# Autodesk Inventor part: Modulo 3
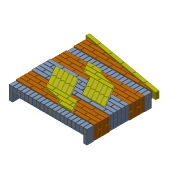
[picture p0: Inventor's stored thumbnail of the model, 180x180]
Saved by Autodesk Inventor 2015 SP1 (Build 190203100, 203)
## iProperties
Created: 2015-04
Part Number: Modulo 3
Material: Generic
Document SubType Name: Modeling
Designer: treina2
Density: 1 g/cm^3
Appearance: Default
Author: treina2
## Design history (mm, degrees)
sketch "Sketch1"
  geometry: L1 (994.875, 828.16)-(1008.247, 805) reference; L2 (1109.875, 329)-(1109.875, 387) reference; L3 (1109.875, 387)-(869.875, 387) reference; L4 (869.875, 387)-(869.875, 329) reference; L5 (340.73, 319)-(244.875, 319) reference; L6 (244.875, 319)-(244.875, 261) reference; L7 (939.842, 183)-(836.807, 183) reference; L8 (939.842, 183)-(744.875, 183) reference; L9 (744.875, 183)-(744.875, 125) reference; L10 (861.322, 319)-(836.807, 319) reference; L11 (739.101, 329)-(859.875, 329) reference; L12 (859.875, 329)-(859.875, 387) reference; L13 (859.875, 387)-(705.615, 387) reference; L14 (1234.875, 941)-(994.875, 941) reference; L15 (994.875, 941)-(994.875, 999) reference; L16 (994.875, 999)-(1234.875, 999) reference; L17 (1234.875, 999)-(1234.875, 941) reference; L18 (619.875, 1134)-(859.875, 1134) reference; L19 (859.875, 1134)-(859.875, 1192) reference; L20 (859.875, 1192)-(619.875, 1192) reference; L21 (619.875, 1192)-(619.875, 1134) reference; L22 (136.5, 0)-(136.5, 115) reference; L23 (136.5, 115)-(194.5, 115) reference; L24 (194.5, 115)-(194.5, 0) reference; L25 (194.5, 0)-(136.5, 0) reference; L26 (859.875, 125)-(973.328, 125) reference; L27 (494.875, 669)-(682.621, 669) reference; L28 (119.875, 465)-(256.437, 465) reference; L29 (301.47, 659)-(234.497, 659) reference; L30 (234.497, 659)-(335.632, 483.83) reference; L31 (335.632, 483.83)-(385.861, 512.83) reference; L32 (385.861, 512.83)-(301.47, 659) reference; L33 (-5.125, 261)-(234.875, 261) reference; L34 (234.875, 261)-(234.875, 319) reference; L35 (234.875, 319)-(-5.125, 319) reference; L36 (-5.125, 319)-(-5.125, 261) reference; L37 (832.83, 329)-(859.875, 329) reference; L38 (859.875, 329)-(859.875, 387) reference; L39 (859.875, 387)-(809.762, 387) reference; L40 (619.875, 193)-(642.243, 193) reference; L41 (340.73, 319)-(244.875, 319) reference; L42 (244.875, 319)-(244.875, 261) reference; L43 (619.875, 197.266)-(619.875, 193) reference; L44 (334.956, 329)-(301.47, 387) reference; L45 (494.875, 261)-(734.875, 261) reference; L46 (244.875, 261)-(369.875, 261) reference; L47 (491.996, 329)-(390.861, 504.17) reference; L48 (744.875, 261)-(849.113, 261) reference; L49 (900.582, 251)-(869.875, 251) reference; L50 (869.875, 251)-(869.875, 193) reference; L51 (385.763, 261)-(352.277, 319) reference; L52 (695.615, 193)-(859.875, 193) reference; L53 (859.875, 193)-(859.875, 251) reference; L54 (859.875, 251)-(619.875, 251) reference; L55 (619.875, 251)-(619.875, 207.447) reference; L56 (945.615, 193)-(1109.875, 193) reference; L57 (1109.875, 193)-(1109.875, 251) reference; L58 (1109.875, 251)-(912.129, 251) reference; L59 (906.355, 261)-(984.875, 261) reference; L60 (984.875, 261)-(984.875, 319) reference; L61 (984.875, 319)-(872.869, 319) reference; L62 (144.431, 659)-(119.875, 659) reference; L63 (119.875, 659)-(119.875, 601) reference; L64 (1234.875, 805)-(1008.247, 805) reference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; 3 further points
  constraints: 1806 end point, 395 horizontal, 258 vertical, 116 point on line, 1005 other
workplane "Work Plane1"
sketch "Sketch2"
  geometry: L1 (0, 1009)-(0, 1124) reference; L2 (0, 1124)-(58, 1124) reference; L3 (58, 1124)-(58, 1009) reference; L4 (58, 1009)-(0, 1009) reference; L5 (0, 0)-(0, 115) reference; L6 (0, 115)-(58, 115) reference; L7 (58, 115)-(58, 0) reference; L8 (58, 0)-(0, 0) reference; L9 (126.25, 1124)-(126.25, 1009) reference; L10 (68.25, 1124)-(126.25, 1124) reference; L11 (68.25, 1009)-(68.25, 1124) reference; L12 (126.25, 1009)-(68.25, 1009) reference; L13 (1354.75, 1124)-(1354.75, 1009) reference; L14 (1296.75, 1124)-(1354.75, 1124) reference; L15 (1296.75, 1009)-(1296.75, 1124) reference; L16 (1354.75, 1009)-(1296.75, 1009) reference; L17 (68.25, 0)-(68.25, 115) reference; L18 (68.25, 115)-(126.25, 115) reference; L19 (126.25, 115)-(126.25, 0) reference; L20 (126.25, 0)-(68.25, 0) reference; L21 (1296.75, 0)-(1296.75, 115) reference; L22 (1296.75, 115)-(1354.75, 115) reference; L23 (1354.75, 115)-(1354.75, 0) reference; L24 (1354.75, 0)-(1296.75, 0) reference; 1 further point
extrude "Extrusion2" new body sketch "Sketch2" distance "d6" = 240; taper "d7" = 0 deg
extrude "Extrusion3" new body sketch "Sketch2" distance "d8" = 240; taper "d9" = 0 deg
extrude "Extrusion4" new body sketch "Sketch2" distance "d10" = 240; taper "d11" = 0 deg
extrude "Extrusion5" new body sketch "Sketch2" distance "d12" = 240; taper "d13" = 0 deg
extrude "Extrusion6" new body sketch "Sketch2" distance "d14" = 115; taper "d15" = 0 deg
extrude "Extrusion7" new body sketch "Sketch2" distance "d16" = 115; taper "d17" = 0 deg
extrude "Extrusion8" new body sketch "Sketch1" distance "d24" = 115; taper "d25" = 0 deg
extrude "Extrusion9" new body sketch "Sketch1" distance "d26" = 240; taper "d27" = 0 deg
extrude "Extrusion10" new body sketch "Sketch1" distance "d28" = 240; taper "d29" = 0 deg
extrude "Extrusion11" new body sketch "Sketch1" distance "d30" = 115; taper "d31" = 0 deg
extrude "Extrusion12" new body sketch "Sketch1" distance "d32" = 115; taper "d33" = 0 deg
extrude "Extrusion13" new body sketch "Sketch1" distance "d34" = 115; taper "d35" = 0 deg
extrude "Extrusion14" new body sketch "Sketch1" distance "d36" = 115; taper "d37" = 0 deg
extrude "Extrusion15" new body sketch "Sketch1" distance "d38" = 115; taper "d39" = 0 deg
extrude "Extrusion16" new body sketch "Sketch1" distance "d40" = 115; taper "d41" = 0 deg
extrude "Extrusion17" new body sketch "Sketch1" distance "d42" = 115; taper "d43" = 0 deg
extrude "Extrusion18" new body sketch "Sketch1" distance "d44" = 115; taper "d45" = 0 deg
extrude "Extrusion19" new body sketch "Sketch1" distance "d46" = 115; taper "d47" = 0 deg
extrude "Extrusion20" new body sketch "Sketch1" distance "d48" = 115; taper "d49" = 0 deg
extrude "Extrusion21" new body sketch "Sketch1" distance "d50" = 115; taper "d51" = 0 deg
extrude "Extrusion22" new body sketch "Sketch1" distance "d52" = 115; taper "d53" = 0 deg
extrude "Extrusion23" new body sketch "Sketch1" distance "d54" = 115; taper "d55" = 0 deg
extrude "Extrusion24" new body sketch "Sketch1" distance "d56" = 115; taper "d57" = 0 deg
extrude "Extrusion25" new body sketch "Sketch1" distance "d58" = 115; taper "d59" = 0 deg
extrude "Extrusion26" new body sketch "Sketch1" distance "d60" = 115; taper "d61" = 0 deg
extrude "Extrusion27" new body sketch "Sketch1" distance "d62" = 115; taper "d63" = 0 deg
extrude "Extrusion28" new body sketch "Sketch1" distance "d64" = 115; taper "d65" = 0 deg
extrude "Extrusion29" new body sketch "Sketch1" distance "d66" = 115; taper "d67" = 0 deg
extrude "Extrusion30" new body sketch "Sketch1" distance "d68" = 115; taper "d69" = 0 deg
extrude "Extrusion31" new body sketch "Sketch1" distance "d70" = 115; taper "d71" = 0 deg
extrude "Extrusion32" new body sketch "Sketch1" distance "d72" = 115; taper "d73" = 0 deg
extrude "Extrusion33" new body sketch "Sketch1" distance "d74" = 115; taper "d75" = 0 deg
extrude "Extrusion34" new body sketch "Sketch1" distance "d76" = 115; taper "d77" = 0 deg
extrude "Extrusion35" new body sketch "Sketch1" distance "d78" = 115; taper "d79" = 0 deg
extrude "Extrusion36" new body sketch "Sketch1" distance "d80" = 115; taper "d81" = 0 deg
extrude "Extrusion37" new body sketch "Sketch1" distance "d82" = 240; taper "d83" = 0 deg
extrude "Extrusion38" new body sketch "Sketch1" distance "d84" = 240; taper "d85" = 0 deg
extrude "Extrusion39" new body sketch "Sketch1" distance "d86" = 240; taper "d87" = 0 deg
extrude "Extrusion40" new body sketch "Sketch1" distance "d88" = 240; taper "d89" = 0 deg
extrude "Extrusion41" new body sketch "Sketch1" distance "d90" = 115; taper "d91" = 0 deg
extrude "Extrusion42" new body sketch "Sketch1" distance "d92" = 115; taper "d93" = 0 deg
extrude "Extrusion43" new body sketch "Sketch1" distance "d94" = 115; taper "d95" = 0 deg
extrude "Extrusion44" new body sketch "Sketch1" distance "d96" = 115; taper "d97" = 0 deg
extrude "Extrusion45" new body sketch "Sketch1" distance "d98" = 115; taper "d99" = 0 deg
extrude "Extrusion46" new body sketch "Sketch1" distance "d100" = 115; taper "d101" = 0 deg
extrude "Extrusion47" new body sketch "Sketch1" distance "d102" = 115; taper "d103" = 0 deg
extrude "Extrusion48" new body sketch "Sketch1" distance "d104" = 115; taper "d105" = 0 deg
extrude "Extrusion49" new body sketch "Sketch1" distance "d106" = 115; taper "d107" = 0 deg
extrude "Extrusion50" new body sketch "Sketch1" distance "d108" = 115; taper "d109" = 0 deg
extrude "Extrusion51" new body sketch "Sketch1" distance "d110" = 115; taper "d111" = 0 deg
extrude "Extrusion52" new body sketch "Sketch1" distance "d112" = 115; taper "d113" = 0 deg
extrude "Extrusion53" new body sketch "Sketch1" distance "d114" = 240; taper "d115" = 0 deg
extrude "Extrusion54" new body sketch "Sketch1" distance "d116" = 240; taper "d117" = 0 deg
extrude "Extrusion68" new body sketch "Sketch1" distance "d144" = 240; taper "d145" = 0 deg
extrude "Extrusion69" new body sketch "Sketch1" distance "d146" = 240; taper "d147" = 0 deg
extrude "Extrusion70" new body sketch "Sketch1" distance "d148" = 115; taper "d149" = 0 deg
extrude "Extrusion71" new body sketch "Sketch1" distance "d150" = 115; taper "d151" = 0 deg
extrude "Extrusion72" new body sketch "Sketch1" distance "d152" = 115; taper "d153" = 0 deg
extrude "Extrusion73" new body sketch "Sketch1" distance "d154" = 115; taper "d155" = 0 deg
extrude "Extrusion74" new body sketch "Sketch1" distance "d156" = 115; taper "d157" = 0 deg
extrude "Extrusion75" new body sketch "Sketch1" distance "d158" = 115; taper "d159" = 0 deg
extrude "Extrusion76" new body sketch "Sketch1" distance "d160" = 115; taper "d161" = 0 deg
extrude "Extrusion77" new body sketch "Sketch1" distance "d162" = 115; taper "d163" = 0 deg
extrude "Extrusion78" new body sketch "Sketch1" distance "d164" = 115; taper "d165" = 0 deg
extrude "Extrusion79" new body sketch "Sketch1" distance "d166" = 115; taper "d167" = 0 deg
workplane "Work Plane2"
sketch "Sketch3"
  geometry: L1 (-5.125, 669)-(234.875, 669) reference; L2 (234.875, 727)-(-5.125, 727) reference; L3 (-5.125, 727)-(-5.125, 669) reference; L4 (234.875, 669)-(234.875, 727) reference; L5 (244.875, 727)-(244.875, 669) reference; L6 (392.943, 727)-(244.875, 727) reference; L7 (244.875, 669)-(369.875, 669) reference; L8 (380.637, 669)-(682.621, 669) reference; L9 (484.875, 727)-(244.875, 727) reference; L10 (484.875, 669)-(484.875, 727) reference; L11 (494.875, 727)-(494.875, 669) reference; L12 (649.135, 727)-(494.875, 727) reference; L13 (244.875, 669)-(484.875, 669) reference; L14 (682.621, 669)-(649.135, 727) reference; L15 (582.062, 601)-(609.875, 601) reference; L16 (609.875, 601)-(609.875, 659) reference; L17 (609.875, 659)-(548.576, 659) reference; L18 (548.576, 659)-(582.062, 601) reference; L19 (619.875, 659)-(619.875, 601) reference; L20 (688.395, 659)-(619.875, 659) reference; L21 (721.881, 601)-(688.395, 659) reference; L22 (619.875, 601)-(721.881, 601) reference; L23 (727.654, 591)-(587.836, 591) reference; L24 (734.875, 578.494)-(727.654, 591) reference; L25 (734.875, 533)-(734.875, 578.494) reference; L26 (621.322, 533)-(734.875, 533) reference; L27 (621.322, 533)-(587.836, 591) reference; L28 (660.582, 465)-(627.096, 523) reference; L29 (766.914, 523)-(627.096, 523) reference; L30 (800.401, 465)-(766.914, 523) reference; L31 (660.582, 465)-(800.401, 465) reference; L32 (744.875, 533)-(761.141, 533) reference; L33 (744.875, 561.173)-(744.875, 533) reference; L34 (761.141, 533)-(744.875, 561.173) reference; L35 (699.842, 397)-(734.875, 397) reference; L36 (734.875, 397)-(734.875, 455) reference; L37 (699.842, 397)-(666.355, 455) reference; L38 (734.875, 455)-(666.355, 455) reference; L39 (744.875, 455)-(744.875, 397) reference; L40 (984.875, 455)-(744.875, 455) reference; L41 (744.875, 397)-(849.113, 397) reference; L42 (859.875, 397)-(984.875, 397) reference; L43 (984.875, 397)-(984.875, 455) reference; L44 (744.875, 397)-(984.875, 397) reference; L45 (994.875, 455)-(1234.875, 455) reference; L46 (994.875, 397)-(994.875, 455) reference; L47 (1234.875, 397)-(994.875, 397) reference; L48 (1234.875, 455)-(1234.875, 397) reference; L49 (1359.875, 455)-(1244.875, 455) reference; L50 (1244.875, 455)-(1244.875, 397) reference; L51 (1244.875, 397)-(1359.875, 397) reference; L52 (1359.875, 397)-(1359.875, 455) reference; L53 (1359.875, 465)-(1204.546, 465) reference; L54 (1359.875, 523)-(1359.875, 465) reference; L55 (1171.059, 523)-(1359.875, 523) reference; L56 (1171.059, 523)-(1204.546, 465) reference; L57 (1234.875, 533)-(1165.286, 533) reference; L58 (1234.875, 591)-(1234.875, 533) reference; L59 (1131.8, 591)-(1234.875, 591) reference; L60 (1131.8, 591)-(1165.286, 533) reference; L61 (1359.875, 601)-(1126.026, 601) reference; L62 (1119.875, 611.654)-(1126.026, 601) reference; L63 (1119.875, 611.654)-(1119.875, 659) reference; L64 (1109.875, 628.975)-(1109.875, 659) reference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; 1 further point
extrude "Extrusion80" new body sketch "Sketch3" distance "d169" = 115; taper "d170" = 0 deg
extrude "Extrusion81" new body sketch "Sketch3" distance "d171" = 115; taper "d172" = 0 deg
extrude "Extrusion82" new body sketch "Sketch3" distance "d173" = 115; taper "d174" = 0 deg
extrude "Extrusion83" new body sketch "Sketch3" distance "d175" = 115; taper "d176" = 0 deg
extrude "Extrusion84" new body sketch "Sketch3" distance "d177" = 115; taper "d178" = 0 deg
extrude "Extrusion85" new body sketch "Sketch3" distance "d179" = 115; taper "d180" = 0 deg
extrude "Extrusion86" new body sketch "Sketch3" distance "d181" = 115; taper "d182" = 0 deg
extrude "Extrusion87" new body sketch "Sketch3" distance "d183" = 115; taper "d184" = 0 deg
extrude "Extrusion88" new body sketch "Sketch3" distance "d185" = 115; taper "d186" = 0 deg
extrude "Extrusion89" new body sketch "Sketch3" distance "d187" = 115; taper "d188" = 0 deg
extrude "Extrusion90" new body sketch "Sketch3" distance "d189" = 115; taper "d190" = 0 deg
extrude "Extrusion91" new body sketch "Sketch3" distance "d191" = 115; taper "d192" = 0 deg
extrude "Extrusion92" new body sketch "Sketch3" distance "d193" = 115; taper "d194" = 0 deg
extrude "Extrusion93" new body sketch "Sketch3" distance "d195" = 115; taper "d196" = 0 deg
extrude "Extrusion94" new body sketch "Sketch3" distance "d197" = 115; taper "d198" = 0 deg
extrude "Extrusion95" new body sketch "Sketch3" distance "d199" = 115; taper "d200" = 0 deg
extrude "Extrusion96" new body sketch "Sketch3" distance "d201" = 115; taper "d202" = 0 deg
extrude "Extrusion97" new body sketch "Sketch3" distance "d203" = 115; taper "d204" = 0 deg
extrude "Extrusion98" new body sketch "Sketch3" distance "d205" = 115; taper "d206" = 0 deg
extrude "Extrusion99" new body sketch "Sketch3" distance "d207" = 115; taper "d208" = 0 deg
extrude "Extrusion100" new body sketch "Sketch3" distance "d209" = 115; taper "d210" = 0 deg
extrude "Extrusion101" new body sketch "Sketch3" distance "d211" = 240; taper "d212" = 0 deg
extrude "Extrusion102" new body sketch "Sketch3" distance "d213" = 240; taper "d214" = 0 deg
extrude "Extrusion103" new body sketch "Sketch3" distance "d215" = 240; taper "d216" = 0 deg
extrude "Extrusion104" new body sketch "Sketch3" distance "d217" = 240; taper "d218" = 0 deg
extrude "Extrusion105" new body sketch "Sketch3" distance "d219" = 240; taper "d220" = 0 deg
workplane "Work Plane3"
sketch "Sketch4"
  geometry: L1 (-46.235, 1450.984)-(190.119, 1409.309) reference; L2 (190.119, 1409.309)-(180.047, 1352.19) reference; L3 (-56.307, 1393.865)-(-46.235, 1450.984) reference; L4 (180.047, 1352.19)-(-56.307, 1393.865) reference; L5 (199.967, 1407.572)-(436.321, 1365.897) reference; L6 (189.895, 1350.453)-(199.967, 1407.572) reference; L7 (436.321, 1365.897)-(426.249, 1308.778) reference; L8 (436.097, 1307.041)-(446.169, 1364.16) reference; L9 (446.169, 1364.16)-(682.523, 1322.485) reference; L10 (682.299, 1263.629)-(692.371, 1320.748) reference; L11 (692.371, 1320.748)-(928.724, 1279.072) reference; L12 (682.523, 1322.485)-(672.451, 1265.366) reference; L13 (928.501, 1220.217)-(938.573, 1277.336) reference; L14 (928.724, 1279.072)-(918.653, 1221.954) reference; L15 (938.573, 1277.336)-(1174.926, 1235.66) reference; L16 (1174.703, 1176.805)-(1184.775, 1233.924) reference; L17 (1174.926, 1235.66)-(1164.855, 1178.542) reference; L18 (1184.775, 1233.924)-(1421.128, 1192.248) reference; L19 (1411.057, 1135.13)-(1174.703, 1176.805) reference; L20 (1421.128, 1192.248)-(1411.057, 1135.13) reference; 3 further points
  constraints: 1 other
extrude "Extrusion106" new body sketch "Sketch4" distance "d222" = 115; taper "d223" = 0 deg
extrude "Extrusion107" new body sketch "Sketch4" distance "d224" = 115; taper "d225" = 0 deg
extrude "Extrusion108" new body sketch "Sketch4" distance "d226" = 115; taper "d227" = 0 deg
extrude "Extrusion109" new body sketch "Sketch4" distance "d228" = 115; taper "d229" = 0 deg
extrude "Extrusion110" new body sketch "Sketch4" distance "d230" = 115; taper "d231" = 0 deg
extrude "Extrusion111" new body sketch "Sketch4" distance "d232" = 115; taper "d233" = 0 deg
workplane "Work Plane4"
sketch "Sketch5"
  geometry: L1 (994.875, 828.16)-(1008.247, 805) reference; L2 (1109.875, 329)-(1109.875, 387) reference; L3 (1109.875, 387)-(869.875, 387) reference; L4 (869.875, 387)-(869.875, 329) reference; L5 (340.73, 319)-(244.875, 319) reference; L6 (244.875, 319)-(244.875, 261) reference; L7 (939.842, 183)-(836.807, 183) reference; L8 (939.842, 183)-(744.875, 183) reference; L9 (744.875, 183)-(744.875, 125) reference; L10 (861.322, 319)-(836.807, 319) reference; L11 (739.101, 329)-(859.875, 329) reference; L12 (859.875, 329)-(859.875, 387) reference; L13 (859.875, 387)-(705.615, 387) reference; L14 (1234.875, 941)-(994.875, 941) reference; L15 (994.875, 941)-(994.875, 999) reference; L16 (994.875, 999)-(1234.875, 999) reference; L17 (1234.875, 999)-(1234.875, 941) reference; L18 (619.875, 1134)-(859.875, 1134) reference; L19 (859.875, 1134)-(859.875, 1192) reference; L20 (859.875, 1192)-(619.875, 1192) reference; L21 (619.875, 1192)-(619.875, 1134) reference; L22 (136.5, 0)-(136.5, 115) reference; L23 (136.5, 115)-(194.5, 115) reference; L24 (194.5, 115)-(194.5, 0) reference; L25 (194.5, 0)-(136.5, 0) reference; L26 (859.875, 125)-(973.328, 125) reference; L27 (494.875, 669)-(682.621, 669) reference; L28 (119.875, 465)-(256.437, 465) reference; L29 (301.47, 659)-(234.497, 659) reference; L30 (234.497, 659)-(335.632, 483.83) reference; L31 (335.632, 483.83)-(385.861, 512.83) reference; L32 (385.861, 512.83)-(301.47, 659) reference; L33 (-5.125, 261)-(234.875, 261) reference; L34 (234.875, 261)-(234.875, 319) reference; L35 (234.875, 319)-(-5.125, 319) reference; L36 (-5.125, 319)-(-5.125, 261) reference; L37 (832.83, 329)-(859.875, 329) reference; L38 (859.875, 329)-(859.875, 387) reference; L39 (859.875, 387)-(809.762, 387) reference; L40 (619.875, 193)-(642.243, 193) reference; L41 (340.73, 319)-(244.875, 319) reference; L42 (244.875, 319)-(244.875, 261) reference; L43 (619.875, 197.266)-(619.875, 193) reference; L44 (334.956, 329)-(301.47, 387) reference; L45 (494.875, 261)-(734.875, 261) reference; L46 (244.875, 261)-(369.875, 261) reference; L47 (491.996, 329)-(390.861, 504.17) reference; L48 (744.875, 261)-(849.113, 261) reference; L49 (900.582, 251)-(869.875, 251) reference; L50 (869.875, 251)-(869.875, 193) reference; L51 (385.763, 261)-(352.277, 319) reference; L52 (695.615, 193)-(859.875, 193) reference; L53 (859.875, 193)-(859.875, 251) reference; L54 (859.875, 251)-(619.875, 251) reference; L55 (619.875, 251)-(619.875, 207.447) reference; L56 (945.615, 193)-(1109.875, 193) reference; L57 (1109.875, 193)-(1109.875, 251) reference; L58 (1109.875, 251)-(912.129, 251) reference; L59 (906.355, 261)-(984.875, 261) reference; L60 (984.875, 261)-(984.875, 319) reference; L61 (984.875, 319)-(872.869, 319) reference; L62 (144.431, 659)-(119.875, 659) reference; L63 (119.875, 659)-(119.875, 601) reference; L64 (1234.875, 805)-(1008.247, 805) reference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; 4 further points
  constraints: 1806 end point, 395 horizontal, 258 vertical, 116 point on line, 1005 other
extrude "Extrusion112" new body sketch "Sketch5" distance "d235" = 115; taper "d236" = 0 deg
extrude "Extrusion113" new body sketch "Sketch5" distance "d237" = 115; taper "d238" = 0 deg
extrude "Extrusion114" new body sketch "Sketch5" distance "d239" = 115; taper "d240" = 0 deg
extrude "Extrusion115" new body sketch "Sketch5" distance "d241" = 115; taper "d242" = 0 deg
extrude "Extrusion116" new body sketch "Sketch5" distance "d243" = 115; taper "d244" = 0 deg
extrude "Extrusion117" new body sketch "Sketch5" distance "d245" = 115; taper "d246" = 0 deg
extrude "Extrusion118" new body sketch "Sketch5" distance "d247" = 115; taper "d248" = 0 deg
extrude "Extrusion119" new body sketch "Sketch5" distance "d249" = 115; taper "d250" = 0 deg
extrude "Extrusion120" new body sketch "Sketch5" distance "d251" = 115; taper "d252" = 0 deg
extrude "Extrusion121" new body sketch "Sketch5" distance "d253" = 115; taper "d254" = 0 deg
extrude "Extrusion122" new body sketch "Sketch5" distance "d255" = 115; taper "d256" = 0 deg
extrude "Extrusion123" new body sketch "Sketch5" distance "d257" = 115; taper "d258" = 0 deg
extrude "Extrusion124" new body sketch "Sketch5" distance "d259" = 115; taper "d260" = 0 deg
extrude "Extrusion125" new body sketch "Sketch5" distance "d261" = 115; taper "d262" = 0 deg
extrude "Extrusion126" new body sketch "Sketch5" distance "d263" = 115; taper "d264" = 0 deg
extrude "Extrusion127" new body sketch "Sketch5" distance "d265" = 115; taper "d266" = 0 deg
extrude "Extrusion128" new body sketch "Sketch5" distance "d267" = 115; taper "d268" = 0 deg
extrude "Extrusion129" new body sketch "Sketch5" distance "d269" = 115; taper "d270" = 0 deg
extrude "Extrusion130" new body sketch "Sketch5" distance "d271" = 115; taper "d272" = 0 deg
extrude "Extrusion131" new body sketch "Sketch5" distance "d273" = 115; taper "d274" = 0 deg
extrude "Extrusion132" new body sketch "Sketch5" distance "d275" = 115; taper "d276" = 0 deg
extrude "Extrusion133" new body sketch "Sketch5" distance "d277" = 115; taper "d278" = 0 deg
extrude "Extrusion134" new body sketch "Sketch5" distance "d279" = 115; taper "d280" = 0 deg
extrude "Extrusion135" new body sketch "Sketch5" distance "d281" = 115; taper "d282" = 0 deg
extrude "Extrusion136" new body sketch "Sketch5" distance "d283" = 115; taper "d284" = 0 deg
extrude "Extrusion137" new body sketch "Sketch5" distance "d285" = 115; taper "d286" = 0 deg
extrude "Extrusion138" new body sketch "Sketch5" distance "d287" = 115; taper "d288" = 0 deg
extrude "Extrusion139" new body sketch "Sketch5" distance "d289" = 115; taper "d290" = 0 deg
extrude "Extrusion140" new body sketch "Sketch5" distance "d291" = 115; taper "d292" = 0 deg
extrude "Extrusion141" new body sketch "Sketch5" distance "d293" = 115; taper "d294" = 0 deg
extrude "Extrusion142" new body sketch "Sketch5" distance "d295" = 115; taper "d296" = 0 deg
extrude "Extrusion143" new body sketch "Sketch5" distance "d297" = 115; taper "d298" = 0 deg
extrude "Extrusion144" new body sketch "Sketch5" distance "d299" = 115; taper "d300" = 0 deg
extrude "Extrusion145" new body sketch "Sketch5" distance "d301" = 115; taper "d302" = 0 deg
extrude "Extrusion146" new body sketch "Sketch5" distance "d303" = 115; taper "d304" = 0 deg
extrude "Extrusion147" new body sketch "Sketch5" distance "d305" = 115; taper "d306" = 0 deg
workplane "Work Plane5"
sketch "Sketch6"
  geometry: L1 (-1119.875, 931)-(-1359.875, 931) reference; L2 (-1359.875, 873)-(-1244.875, 873); L3 (-1244.875, 873)-(-1244.875, 931); L4 (-1244.875, 931)-(-1359.875, 931); L5 (-1359.875, 931)-(-1359.875, 873); 1 further point
  constraints: 8 end point, 2 parallel, 1 horizontal, 1 perpendicular, 1 point on line
  dimensions: "d308" = 115 distance between parallel lines of L5 L3
extrude "Extrusion148" new body sketch "Sketch6" stored distance "d309" = 115; taper "d310" = 0 deg
pattern_linear "Rectangular Pattern5" dims "d316" = 136
workplane "Work Plane6"
sketch "Sketch7"
  geometry: L1 (-1119.875, 659)-(-1359.875, 659) reference; L2 (-1359.875, 601)-(-1244.875, 601); L3 (-1244.875, 601)-(-1244.875, 659); L4 (-1244.875, 659)-(-1359.875, 659); L5 (-1359.875, 659)-(-1359.875, 601); 1 further point
  constraints: 8 end point, 2 parallel, 1 horizontal, 1 perpendicular, 1 point on line
  dimensions: "d318" = 115 distance between parallel lines of L5 L3
extrude "Extrusion149" new body sketch "Sketch7" distance "d319" = 115; taper "d320" = 0 deg
pattern_linear "Rectangular Pattern6" dims "d323" = 136
workplane "Work Plane7"
sketch "Sketch8"
  geometry: L1 (-1119.875, 387)-(-1359.875, 387) reference; L2 (-1359.875, 329)-(-1244.875, 329); L3 (-1244.875, 329)-(-1244.875, 387); L4 (-1244.875, 387)-(-1359.875, 387); L5 (-1359.875, 387)-(-1359.875, 329); 1 further point
  constraints: 8 end point, 2 parallel, 1 horizontal, 1 perpendicular, 1 point on line
  dimensions: "d325" = 115 distance between parallel lines of L5 L3
extrude "Extrusion150" new body sketch "Sketch8" distance "d326" = 115; taper "d327" = 0 deg
pattern_linear "Rectangular Pattern7" dims "d330" = 136
workplane "Work Plane8"
sketch "Sketch9"
  geometry: L1 (-234.875, 1202)-(5.125, 1202) reference; L2 (5.125, 1260)-(-109.875, 1260); L3 (-109.875, 1260)-(-109.875, 1202); L4 (-109.875, 1202)-(5.125, 1202); L5 (5.125, 1202)-(5.125, 1260); 1 further point
  constraints: 8 end point, 2 parallel, 1 horizontal, 1 perpendicular, 1 point on line
  dimensions: "d332" = 115 distance between parallel lines of L5 L3
extrude "Extrusion151" new body sketch "Sketch9" distance "d333" = 115; taper "d334" = 0 deg
workplane "Work Plane9"
sketch "Sketch10"
  geometry: L1 (-234.875, 941)-(5.125, 941) reference; L2 (5.125, 999)-(-109.875, 999); L3 (-109.875, 999)-(-109.875, 941); L4 (-109.875, 941)-(5.125, 941); L5 (5.125, 941)-(5.125, 999); 1 further point
  constraints: 8 end point, 2 parallel, 1 horizontal, 1 perpendicular, 1 point on line
  dimensions: "d336" = 115 distance between parallel lines of L5 L3
extrude "Extrusion152" new body sketch "Sketch10" distance "d337" = 115; taper "d338" = 0 deg
pattern_linear "Rectangular Pattern8" dims "d341" = 136
workplane "Work Plane10"
sketch "Sketch11"
  geometry: L1 (-234.875, 669)-(5.125, 669) reference; L2 (5.125, 727)-(-109.875, 727); L3 (-109.875, 727)-(-109.875, 669); L4 (-109.875, 669)-(5.125, 669); L5 (5.125, 669)-(5.125, 727); 1 further point
  constraints: 8 end point, 2 parallel, 1 horizontal, 1 perpendicular, 1 point on line
  dimensions: "d343" = 115 distance between parallel lines of L5 L3
extrude "Extrusion153" new body sketch "Sketch11" distance "d344" = 115; taper "d345" = 0 deg
pattern_linear "Rectangular Pattern9" dims "d348" = 136
workplane "Work Plane11"
sketch "Sketch12"
  geometry: L1 (5.125, 319)-(-109.875, 319); L2 (-109.875, 319)-(-109.875, 261); L3 (-109.875, 261)-(5.125, 261); L4 (5.125, 261)-(5.125, 319); 1 further point
  constraints: 8 end point, 2 parallel, 1 horizontal, 1 perpendicular
  dimensions: "d350" = 115 distance between parallel lines of L4 L2
extrude "Extrusion154" new body sketch "Sketch12" distance "d351" = 115; taper "d352" = 0 deg
pattern_linear "Rectangular Pattern10" dims "d355" = 136
workplane "Work Plane12"
sketch "Sketch14"
  geometry: L1 (-109.875, 1338)-(-109.875, 1354.409); L2 (5.125, 1338)-(-109.875, 1338); L3 (-202.934, 1338)-(5.125, 1338) reference; L4 (5.125, 1374.686)-(-109.875, 1354.409); L5 (5.125, 1374.686)-(-202.934, 1338) reference; L6 (5.125, 1338)-(5.125, 1374.686); L7 (5.125, 1338)-(5.125, 1374.686) reference; 2 further points
  constraints: 8 end point, 2 point on line, 1 collinear, 1 vertical
extrude "Extrusion155" new body sketch "Sketch14" distance "d357" = 115; taper "d358" = 0 deg
workplane "Work Plane13"
sketch "Sketch15"
  geometry: L1 (621.422, 795)-(811.948, 465); L2 (722.556, 619.83)-(621.422, 795) reference; L3 (811.948, 465)-(1192.999, 465); L4 (1192.999, 465)-(1126.026, 465) reference; L5 (1192.999, 465)-(957.44, 873); L6 (957.44, 873)-(653.361, 931); L7 (653.361, 931)-(859.875, 891.61) reference; L8 (653.361, 931)-(614.101, 999); L9 (614.101, 999)-(375.649, 999); L10 (375.649, 999)-(484.875, 999) reference; L11 (375.649, 999)-(487.654, 805); L12 (409.135, 941)-(375.649, 999) reference; L13 (621.422, 795)-(615.649, 805); L14 (734.875, 805)-(494.875, 805) reference; L15 (615.649, 805)-(487.654, 805); L16 (646.99, 922.035)-(951.069, 864.035); L17 (951.069, 864.035)-(1175.678, 475); L18 (1175.678, 475)-(817.721, 475); L19 (817.721, 475)-(630.082, 800); L20 (630.082, 800)-(621.422, 815); L21 (621.422, 815)-(493.428, 815); L22 (493.428, 815)-(392.969, 989); L23 (392.969, 989)-(608.328, 989); L24 (608.328, 989)-(646.99, 922.035); L25 (155.978, 659)-(537.029, 659); L26 (537.029, 659)-(733.328, 319); L27 (626.42, 504.17)-(727.554, 329) reference; L28 (733.328, 319)-(859.875, 319); L29 (859.875, 319)-(971.881, 125); L30 (971.881, 125)-(734.615, 125); L31 (973.328, 125)-(744.875, 125) reference; L32 (734.615, 125)-(695.323, 193.056); L33 (695.323, 193.056)-(391.537, 251); L34 (609.875, 209.354)-(391.537, 251) reference; L35 (391.537, 251)-(155.978, 659); L36 (531.255, 649)-(173.298, 649); L37 (173.298, 649)-(397.908, 259.965); L38 (397.908, 259.965)-(701.694, 202.021); L39 (701.694, 202.021)-(740.388, 135); L40 (740.388, 135)-(954.56, 135); L41 (954.56, 135)-(854.101, 309); L42 (854.101, 309)-(727.554, 309); L43 (727.554, 309)-(531.255, 649); 1 further point
  constraints: 68 end point, 12 parallel, 8 collinear, 1 horizontal, 1 point on line, 15 other
  dimensions: "d360" = 10 distance between parallel lines of L6 L16; "d361" = 10 distance between parallel lines of L25 L36
extrude "Extrusion156" new body sketch "Sketch15" distance "d362" = 95; taper "d363" = 0 deg
workplane "Work Plane14"
sketch "Sketch16"
  geometry: L1 (646.99, 922.035)-(951.069, 864.035) reference; L2 (608.328, 989)-(646.99, 922.035) reference; L3 (392.969, 989)-(608.328, 989) reference; L4 (493.428, 815)-(392.969, 989) reference; L5 (621.422, 815)-(493.428, 815) reference; L6 (817.721, 475)-(621.422, 815) reference; L7 (1175.678, 475)-(817.721, 475) reference; L8 (951.069, 864.035)-(1175.678, 475) reference; L9 (531.255, 649)-(173.298, 649) reference; L10 (173.298, 649)-(397.908, 259.965) reference; L11 (397.908, 259.965)-(701.694, 202.021) reference; L12 (701.694, 202.021)-(740.388, 135) reference; L13 (740.388, 135)-(954.56, 135) reference; L14 (954.56, 135)-(854.101, 309) reference; L15 (854.101, 309)-(727.554, 309) reference; L16 (727.554, 309)-(531.255, 649) reference; L17 (1354.75, 0)-(1296.75, 0) reference; L18 (1344.75, 0)-(10, 0); L19 (58, 0)-(0, 0) reference; L20 (1344.75, 0)-(1344.75, 1195.562); L21 (10, 0)-(10, 1430.914); L22 (-46.235, 1450.984)-(190.119, 1409.309) reference; L23 (1184.775, 1233.924)-(1421.128, 1192.248) reference; L24 (10, 1430.914)-(1344.75, 1195.562); 2 further points
  constraints: 8 end point, 4 point on line, 2 vertical, 1 parallel
  dimensions: "d367" = 10 distance from line of L17.start L20; "d368" = 10 distance from line of L19.end L21 (= d367); "d370" = 10 distance between parallel lines of L24 L22
extrude "Extrusion157" join sketch "Sketch16" distance "d365" = 95; taper "d366" = 0 deg
sketch "Sketch17"
  geometry: L1 (1490.517, 397)-(1490.517, -135.871); L2 (1490.517, -135.871)-(-86.242, -135.871); L3 (-86.242, -135.871)-(-86.242, 397); L4 (-5.125, 397)-(234.875, 397) reference; L5 (-56.307, 1393.865)-(180.047, 1352.19) reference; L6 (531.255, 649)-(173.298, 649) reference; L7 (173.298, 649)-(397.908, 259.965) reference; L8 (397.908, 259.965)-(701.694, 202.021) reference; L9 (701.694, 202.021)-(740.388, 135) reference; L10 (740.388, 135)-(954.56, 135) reference; L11 (954.56, 135)-(854.101, 309) reference; L12 (854.101, 309)-(727.554, 309) reference; L13 (727.554, 309)-(531.255, 649) reference; L14 (646.99, 922.035)-(951.069, 864.035) reference; L15 (608.328, 989)-(646.99, 922.035) reference; L16 (392.969, 989)-(608.328, 989) reference; L17 (493.428, 815)-(392.969, 989) reference; L18 (621.422, 815)-(493.428, 815) reference; L19 (817.721, 475)-(621.422, 815) reference; L20 (1175.678, 475)-(817.721, 475) reference; L21 (951.069, 864.035)-(1175.678, 475) reference; L22 (-86.242, 397)-(318.791, 397); L23 (676.748, 397)-(1490.517, 397); L24 (234.875, 727)-(-5.125, 727) reference; L25 (1174.703, 1176.805)-(1411.057, 1135.13) reference; L26 (1466.859, 727)-(1466.859, 1125.29); L27 (1466.859, 1125.29)-(-78.295, 1397.742); L28 (-78.295, 1397.742)-(-78.295, 727); L29 (-78.295, 727)-(672.229, 727); L30 (1030.186, 727)-(1466.859, 727); 1 further point
  constraints: 20 end point, 5 collinear, 4 horizontal, 4 parallel, 4 perpendicular, 4 point on line
extrude "Extrusion158" cut sketch "Sketch17" distance "d371" = 10; taper "d372" = 0 deg
sketch "Sketch18"
  geometry: L1 (-5.125, 125)-(234.875, 125) reference; L2 (-122.801, -88.829)-(1458.698, -88.829); L3 (1458.698, -88.829)-(1458.698, 125); L4 (1458.698, 125)-(-122.801, 125); L5 (-122.801, 125)-(-122.801, -88.829); L6 (109.875, 1134)-(-5.125, 1134) reference; L7 (234.875, 999)-(-5.125, 999) reference; L8 (-236.658, 1134)-(1551.727, 1134); L9 (1551.727, 1134)-(1551.727, 999); L10 (1551.727, 999)-(-236.658, 999); L11 (-236.658, 999)-(-236.658, 1134); 1 further point
  constraints: 16 end point, 4 parallel, 3 collinear, 2 horizontal, 2 perpendicular
extrude "Extrusion159" cut sketch "Sketch18" distance "d373" = 10; taper "d374" = 0 deg
sketch "Sketch19"
  geometry: L1 (-646.99, 922.035)-(-608.328, 989) reference; L2 (-608.328, 989)-(-392.969, 989) reference; L3 (-392.969, 989)-(-493.428, 815) reference; L4 (-493.428, 815)-(-621.422, 815) reference; L5 (-621.422, 815)-(-817.721, 475) reference; L6 (-817.721, 475)-(-1175.678, 475) reference; L7 (-1175.678, 475)-(-951.069, 864.035) reference; L8 (-951.069, 864.035)-(-646.99, 922.035) reference; L9 (-173.298, 649)-(-397.908, 259.965) reference; L10 (-397.908, 259.965)-(-701.694, 202.021) reference; L11 (-701.694, 202.021)-(-740.388, 135) reference; L12 (-740.388, 135)-(-954.56, 135) reference; L13 (-954.56, 135)-(-854.101, 309) reference; L14 (-854.101, 309)-(-727.554, 309) reference; L15 (-727.554, 309)-(-531.255, 649) reference; L16 (-531.255, 649)-(-173.298, 649) reference; L17 (-1344.75, 0)-(-10, 0) reference; L18 (-10, 0)-(-10, 1430.914) reference; L19 (-10, 1430.914)-(-1344.75, 1195.562) reference; L20 (-1344.75, 1195.562)-(-1344.75, 0) reference; L21 (-666.103, 948.93)-(-625.649, 1019); L22 (-625.649, 1019)-(-341.007, 1019); L23 (-341.007, 1019)-(-476.107, 785); L24 (-476.107, 785)-(-604.101, 785); L25 (-604.101, 785)-(-800.401, 445); L26 (-800.401, 445)-(-1227.64, 445); L27 (-1227.64, 445)-(-970.182, 890.93); L28 (-970.182, 890.93)-(-666.103, 948.93); L29 (-121.337, 679)-(-378.795, 233.07); L30 (-378.795, 233.07)-(-682.581, 175.126); L31 (-682.581, 175.126)-(-723.068, 105); L32 (-723.068, 105)-(-1006.522, 105); L33 (-1006.522, 105)-(-871.422, 339); L34 (-871.422, 339)-(-744.875, 339); L35 (-744.875, 339)-(-548.576, 679); L36 (-548.576, 679)-(-121.337, 679); L37 (-984.875, 845.481)-(-974.76, 863) reference; L38 (-183.691, 591)-(-217.177, 533) reference; 1 further point
  constraints: 32 end point, 14 other
  dimensions: "d377" = 10 distance between parallel lines of L27 L37; "d378" = 10 distance between parallel lines of L29 L38 (= d377)
extrude "Extrusion160" cut sketch "Sketch19" stored distance "d375" = 10; taper "d376" = 0 deg
sketch "Sketch20"
  geometry: L1 (-682.581, 175.126)-(-723.068, 105) reference; L2 (-723.068, 105)-(-1006.522, 105) reference; L3 (-1006.522, 105)-(-871.422, 339) reference; L4 (-871.422, 339)-(-744.875, 339) reference; L5 (-744.875, 339)-(-548.576, 679) reference; L6 (-548.576, 679)-(-121.337, 679) reference; L7 (-121.337, 679)-(-378.795, 233.07) reference; L8 (-378.795, 233.07)-(-682.581, 175.126) reference; L9 (-476.107, 785)-(-604.101, 785) reference; L10 (-604.101, 785)-(-800.401, 445) reference; L11 (-800.401, 445)-(-1227.64, 445) reference; L12 (-1227.64, 445)-(-970.182, 890.93) reference; L13 (-970.182, 890.93)-(-666.103, 948.93) reference; L14 (-666.103, 948.93)-(-625.649, 1019) reference; L15 (-625.649, 1019)-(-341.007, 1019) reference; L16 (-341.007, 1019)-(-476.107, 785) reference; L17 (-1344.75, 0)-(-10, 0) reference; L18 (-10, 0)-(-10, 1430.914) reference; L19 (-10, 1430.914)-(-1344.75, 1195.562) reference; L20 (-1344.75, 1195.562)-(-1344.75, 0) reference; L21 (-1244.875, 737)-(-1359.875, 737) reference; L22 (-1244.875, 387)-(-1359.875, 387) reference; L23 (-10, 747)-(-10, 1361.865); L24 (-10, 1361.865)-(-1344.75, 1126.513); L25 (-1344.75, 1126.513)-(-1344.75, 747); L26 (-369.875, 1308.564)-(-588.581, 1270) reference; L27 (-10, 0)-(-10, 1430.914) reference; L28 (-1344.75, 747)-(-1053.28, 747); L29 (-626.041, 747)-(-10, 747); L30 (-1359.875, 125)-(-1244.875, 125) reference; L31 (-10, 377)-(-10, 135); L32 (-1344.75, 135)-(-1344.75, 377); L33 (-1344.75, 1195.562)-(-1344.75, 0) reference; L34 (-1344.75, 377)-(-722.936, 377); L35 (-295.696, 377)-(-10, 377); L36 (-10, 135)-(-705.747, 135); L37 (-989.201, 135)-(-1344.75, 135); 1 further point
  constraints: 22 end point, 6 parallel, 6 point on line, 4 collinear, 4 horizontal, 4 perpendicular, 1 vertical
  dimensions: "d379" = 10 distance between parallel lines of L26 L24
extrude "Extrusion161" join sketch "Sketch20" distance "d383" = 10; taper "d384" = 0 deg
sketch "Sketch21"
  geometry: L1 (-1344.75, 0)-(-10, 0); L2 (-10, 0)-(-10, 105); L3 (-10, 105)-(-1344.75, 105); L4 (-1344.75, 105)-(-1344.75, 0); L5 (-1344.75, 135)-(-1344.75, 0) reference; L6 (-1344.75, 0)-(-10, 0) reference; L7 (-10, 0)-(-10, 135) reference; L8 (0, 115)-(-58, 115) reference; L9 (-1344.75, 1114)-(-10, 1114); L10 (-10, 1114)-(-10, 1019); L11 (-10, 1019)-(-1344.75, 1019); L12 (-1344.75, 1019)-(-1344.75, 1114); L13 (-1296.75, 1124)-(-1354.75, 1124) reference; L14 (-1354.75, 1009)-(-1296.75, 1009) reference; 1 further point
  constraints: 16 end point, 4 parallel, 3 collinear, 2 horizontal, 2 perpendicular
  dimensions: "d385" = 10 distance between parallel lines of L8 L3; "d386" = 10 distance between parallel lines of L13 L9; "d387" = 10 distance between parallel lines of L14 L11 (= d386)
extrude "Extrusion162" join sketch "Sketch21" distance "d388" = 10; taper "d389" = 0 deg
sketch "Sketch22"
  geometry: L1 (-1344.75, 1126.513)-(-1344.75, 747) reference; L2 (-10, 747)-(-10, 1361.865) reference; L3 (-1344.75, 1114)-(-10, 1114); L4 (-10, 1114)-(-10, 1019); L5 (-10, 1019)-(-1344.75, 1019); L6 (-1344.75, 1019)-(-1344.75, 1114); L7 (-1296.75, 1124)-(-1354.75, 1124) reference; L8 (-1354.75, 1009)-(-1296.75, 1009) reference; 1 further point
  constraints: 8 end point, 2 parallel, 2 point on line, 1 horizontal, 1 perpendicular
  dimensions: "d390" = 10 distance between parallel lines of L7 L3; "d391" = 10 distance between parallel lines of L5 L8 (= d390)
extrude "Extrusion163" join sketch "Sketch22" distance "d392" = 10; taper "d393" = 0 deg
workplane "Work Plane15"
sketch "Sketch24"
  geometry: L1 (-10, 1134)-(-10, 1382.174) reference; L2 (-99.875, 115)-(-10, 115); L3 (-10, 115)-(-10, 1335.791); L4 (-10, 1335.791)-(-99.875, 1335.791); L5 (-99.875, 1335.791)-(-99.875, 115); L6 (-109.875, 591)-(-109.875, 533) reference; L7 (-58, 115)-(0, 115) reference; 1 further point
  constraints: 8 end point, 2 parallel, 1 collinear, 1 horizontal, 1 perpendicular, 1 point on line
  dimensions: "d395" = 10 distance between parallel lines of L6 L5
extrude "Extrusion164" join sketch "Sketch24" stored distance "d396" = 10; taper "d397" = 0 deg
sketch "Sketch25"
  geometry: L1 (-10, 115)-(-10, 1335.791) reference; L2 (-1344.75, 999)-(-10, 999) reference; L3 (-10, 1134.492)-(-103.762, 1134.492); L4 (-103.762, 1134.492)-(-103.762, 999); L5 (-103.762, 999)-(-10, 999); L6 (-10, 999)-(-10, 1134.492); L7 (-111.075, 738.325)-(0, 738.325); L8 (0, 738.325)-(0, 385.009); L9 (0, 385.009)-(-111.075, 385.009); L10 (-111.075, 385.009)-(-111.075, 738.325); 1 further point
  constraints: 16 end point, 4 parallel, 2 horizontal, 2 perpendicular, 2 point on line
extrude "Extrusion165" cut sketch "Sketch25" distance "d398" = 10; taper "d399" = 0 deg
sketch "Sketch26"
  geometry: L1 (-99.875, 1134.492)-(-10, 1134.492) reference; L2 (-1344.75, 999)-(-10, 999) reference; L3 (-48, 1134.492)-(-115.509, 1134.492); L4 (-115.509, 1134.492)-(-115.509, 999); L5 (-115.509, 999)-(-48, 999); L6 (-48, 999)-(-48, 1134.492); L7 (-58, 1124)-(-58, 1009) reference; 1 further point
  constraints: 8 end point, 2 parallel, 2 point on line, 1 horizontal, 1 perpendicular
  dimensions: "d400" = 10 distance between parallel lines of L6 L7
extrude "Extrusion166" cut sketch "Sketch26" stored distance "d401" = 10; taper "d402" = 0 deg
sketch "Sketch27"
  geometry: L1 (-10, 125)-(-1344.75, 125) reference; L2 (-48, 107.309)-(-105.202, 107.309); L3 (-105.202, 107.309)-(-105.202, 125); L4 (-105.202, 125)-(-48, 125); L5 (-48, 125)-(-48, 107.309); L6 (-58, 0)-(-58, 115) reference; 1 further point
  constraints: 8 end point, 2 parallel, 1 horizontal, 1 perpendicular, 1 point on line
  dimensions: "d405" = 10 distance between parallel lines of L6 L5
extrude "Extrusion167" cut sketch "Sketch27" stored distance "d403" = 10; taper "d404" = 0 deg
sketch "Sketch28"
  geometry: L1 (-1354.75, 1009)-(-1296.75, 1009) reference; L2 (-1254.875, 115)-(-1344.75, 115); L3 (-1344.75, 115)-(-1344.75, 1009); L4 (-1344.75, 1009)-(-1254.875, 1009); L5 (-1254.875, 1009)-(-1254.875, 115); L6 (-1244.875, 125)-(-1244.875, 183) reference; L7 (-1296.75, 115)-(-1354.75, 115) reference; L8 (-1344.75, 747)-(-1344.75, 377) reference; 1 further point
  constraints: 8 end point, 2 collinear, 2 parallel, 1 horizontal, 1 perpendicular, 1 point on line
  dimensions: "d406" = 10 distance between parallel lines of L6 L5
extrude "Extrusion168" join sketch "Sketch28" stored distance "d407" = 0; taper "d408" = 0 deg
sketch "Sketch29"
  geometry: L1 (-1344.75, 377)-(-1344.75, 747) reference; L2 (-1254.875, 747)-(-1254.875, 377) reference; L3 (-1344.75, 737)-(-1254.875, 737); L4 (-1254.875, 737)-(-1254.875, 387); L5 (-1254.875, 387)-(-1344.75, 387); L6 (-1344.75, 387)-(-1344.75, 737); L7 (-1244.875, 737)-(-1359.875, 737) reference; L8 (-1244.875, 387)-(-1359.875, 387) reference; 1 further point
  constraints: 8 end point, 2 collinear, 2 parallel, 2 point on line, 1 horizontal, 1 perpendicular
extrude "Extrusion169" cut sketch "Sketch29" distance "d409" = 10; taper "d410" = 0 deg
sketch "Sketch30"
  geometry: L1 (-10, 125)-(-1344.75, 125) reference; L2 (-1306.75, 125)-(-1244.759, 125); L3 (-1244.759, 125)-(-1244.759, 91.405); L4 (-1244.759, 91.405)-(-1306.75, 91.405); L5 (-1306.75, 91.405)-(-1306.75, 125); L6 (-1296.75, 0)-(-1296.75, 115) reference; 1 further point
  constraints: 8 end point, 2 parallel, 1 horizontal, 1 perpendicular, 1 point on line
  dimensions: "d411" = 10 distance between parallel lines of L6 L5
extrude "Extrusion170" cut sketch "Sketch30" stored distance "d412" = 10; taper "d413" = 0 deg
sketch "Sketch31"
  geometry: L1 (-1306.75, 999)-(-1216.7, 999); L2 (-1216.7, 999)-(-1216.7, 1043.154); L3 (-1216.7, 1043.154)-(-1306.75, 1043.154); L4 (-1306.75, 1043.154)-(-1306.75, 999); L5 (-1244.875, 999)-(-1359.875, 999) reference; L6 (-1296.75, 1009)-(-1296.75, 1124) reference; 1 further point
  constraints: 8 end point, 2 parallel, 1 collinear, 1 horizontal, 1 perpendicular
  dimensions: "d414" = 10 distance between parallel lines of L6 L4
extrude "Extrusion171" cut sketch "Sketch31" stored distance "d415" = 10; taper "d416" = 0 deg
node "M3.21"
pattern_linear "Rectangular Pattern2" dims "d20" = 68.25
pattern_linear "Rectangular Pattern3" dims "d23" = 68.25
node "M3.22"
node "M3.23"
node "M3.24"
node "M3.25"
node "M3.26"
feature "Pattern of M3.26:20"
node "M3.27"
feature "Pattern of M3.26:21"
node "M3.28"
feature "Pattern of M3.26:22"
node "M3.29"
feature "Pattern of M3.26:23"
node "M3.30"
feature "Pattern of M3.26:24"
node "M3.31"
feature "Pattern of M3.26:25"
node "M3.32"
feature "Pattern of M3.26:26"
node "M3.33"
feature "Pattern of M3.26:27"
node "M3.34"
feature "Pattern of M3.26:28"
node "M3.35"
feature "Pattern of M3.26:29"
node "M3.36"
feature "Pattern of M3.26:30"
node "M3.37"
feature "Pattern of M3.26:31"
node "M3.38"
feature "Pattern of M3.26:32"
node "M3.39"
feature "Pattern of M3.26:33"
node "M3.40"
feature "Pattern of M3.26:34"
node "M3.41"
feature "Pattern of M3.26:35"
node "M3.42"
feature "Pattern of M3.26:36"
node "M3.43"
feature "Pattern of M3.25:37"
node "M3.44"
feature "Pattern of M3.25:38"
node "M3.45"
feature "Pattern of M3.25:39"
node "M3.46"
feature "Pattern of M3.25:40"
node "M3.47"
feature "Pattern of M3.25:41"
node "M3.48"
feature "Pattern of M3.25:42"
node "M3.49"
feature "Pattern of M3.25:43"
node "M3.50"
feature "Pattern of M3.25:44"
node "M3.51"
feature "Pattern of M3.25:45"
node "M3.52"
feature "Pattern of M3.25:46"
node "M3.53"
feature "Pattern of M3.25:47"
node "M3.54"
feature "Pattern of M3.25:48"
node "M3.55"
feature "Pattern of M3.25:49"
node "M3.56"
feature "Pattern of M3.25:50"
node "M3.57"
feature "Pattern of M3.25:51"
node "M3.58"
feature "Pattern of M3.25:52"
node "M3.59"
feature "Pattern of M3.25:53"
node "M3.60"
node "M3.61"
node "M3.62"
node "M3.63"
node "M3.64"
node "M3.65"
node "M3.66"
node "M3.67"
node "M3.68"
node "M3.69"
node "M3.70"
node "M3.71"
node "M3.72"
node "M3.73"
node "M3.74"
node "M3.75"
node "M3.76"
node "M3.77"
node "M3.78"
node "M3.79"
node "M3.80"
node "M3.81"
node "M3.82"
node "M3.83"
node "M3.84"
node "M3.85"
node "M3.86"
node "M3.87"
node "M3.88"
node "M3.89"
node "M3.90"
node "M3.91"
node "M3.92"
node "M3.93"
node "M3.94"
node "M3.95"
node "M3.96"
node "M3.97"
node "M3.98"
node "M3.99"
node "M3.100"
node "M3.101"
node "M3.102"
node "M3.103"
node "M3.104"
node "M3.105"
node "M3.106"
node "M3.107"
node "M3.121"
node "M3.122"
node "M3.123"
node "M3.124"
node "M3.125"
node "M3.126"
node "M3.127"
node "M3.128"
node "M3.129"
node "M3.130"
node "M3.131"
node "M3.132"
node "M3.133"
node "M3.134"
node "M3.135"
node "M3.136"
node "M3.137"
node "M3.138"
node "M3.139"
node "M3.140"
node "M3.141"
node "M3.142"
node "M3.143"
node "M3.144"
node "M3.145"
node "M3.146"
node "M3.147"
node "M3.148"
node "M3.149"
node "M3.150"
node "M3.151"
node "M3.152"
node "M3.153"
node "M3.154"
node "M3.155"
node "M3.156"
node "M3.157"
node "M3.158"
node "M3.159"
node "M3.160"
node "M3.161"
node "M3.162"
node "M3.163"
node "M3.164"
node "M3.165"
node "M3.166"
node "M3.167"
node "M3.168"
node "M3.169"
node "M3.170"
node "M3.171"
node "M3.172"
node "M3.173"
node "M3.174"
node "M3.175"
node "M3.176"
node "M3.177"
node "M3.178"
node "M3.179"
node "M3.180"
node "M3.181"
node "M3.182"
node "M3.183"
node "M3.184"
node "M3.185"
node "M3.186"
node "M3.187"
node "M3.188"
node "M3.189"
node "M3.190"
node "M3.191"
node "M3.192"
node "M3.193"
node "M3.194"
node "M3.195"
node "M3.196"
node "M3.197"
node "M3.198"
node "M3.199"
node "M3.200"
node "M3.201"
node "M3.207"
feature "Pattern of M3.207:59"
node "M3.208"
node "M3.209"
feature "Pattern of M3.209:60"
node "M3.210"
node "M3.211"
node "M3.212"
feature "Pattern of M3.212:61"
node "M3.213"
node "M3.214"
node "M3.215"
feature "Pattern of M3.215:62"
node "M3.216"
feature "Pattern of M3.214:63"
node "M3.217"
feature "Pattern of M3.214:64"
node "M3.218"
node "M3.219"
node "Cimento"
node "Projected Loop1"
node "Projected Loop2"
node "Projected Loop3"
node "Projected Loop4"
node "Projected Loop5"
node "Projected Loop6"
other parameters: "TIJOLO_PADRAO_LARG" = 115, "TIJOLO_PADRAO_PROF" = 58, "AMAR_PADRAO_LARG" = 115, "AMAR_PADRAO_PROF" = 58
